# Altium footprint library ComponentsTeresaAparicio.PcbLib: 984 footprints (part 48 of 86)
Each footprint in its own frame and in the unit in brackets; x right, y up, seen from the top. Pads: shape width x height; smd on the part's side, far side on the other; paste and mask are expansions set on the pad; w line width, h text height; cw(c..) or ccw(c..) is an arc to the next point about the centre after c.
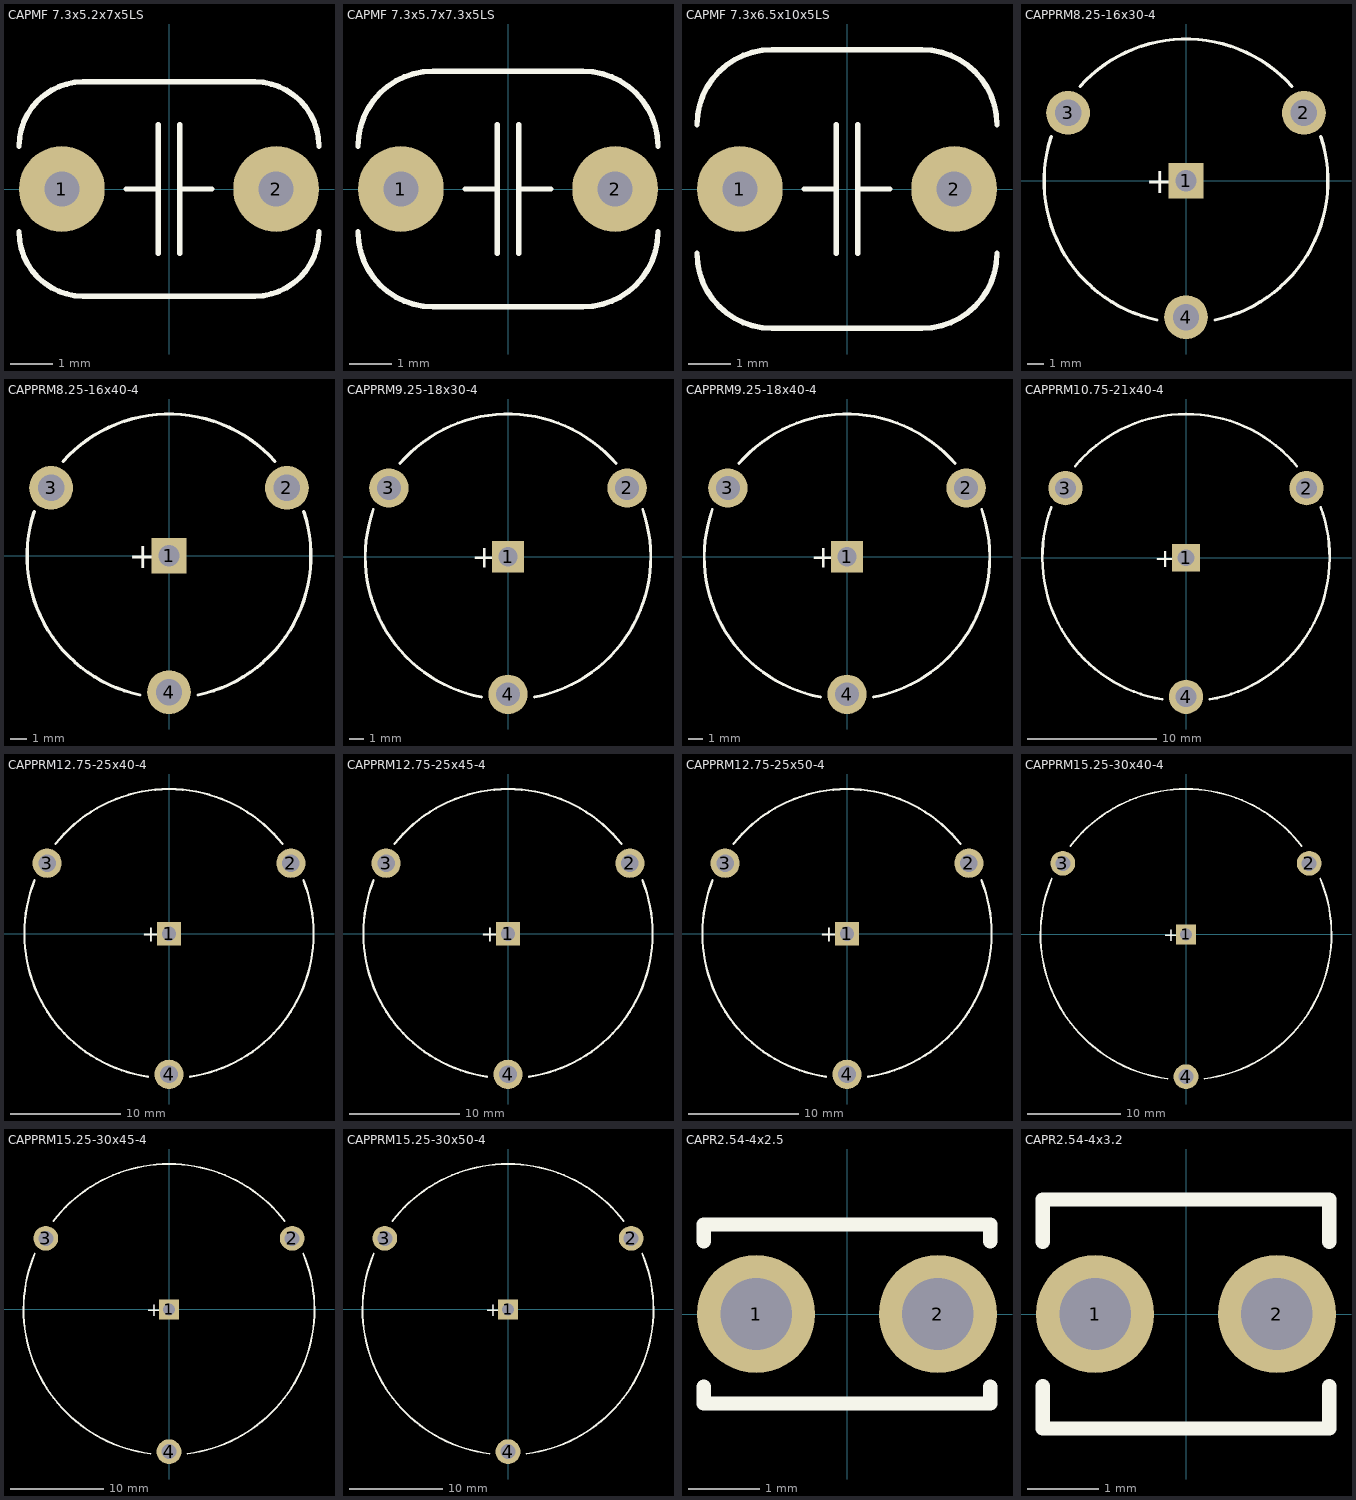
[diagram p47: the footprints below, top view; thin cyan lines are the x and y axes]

## CAPMF 7.3x5.2x7x5LS [mm] "Capacitor, THT, Metallized Polyester Film"
height 7
pads (2):
  round 2 hole 0.813: 1(-2.5,0) 2(2.5,0)
Top Overlay:
  lines w0.127: -3.5,-1 ccw(c-2,-1) -2,-2.5 2,-2.5 ccw(c2,-1) 3.5,-1 ; -3.5,1 cw(c-2,1) -2,2.5 2,2.5 cw(c2,1) 3.5,1 ; -1,0 -0.25,0 ; -0.25,-1.5 -0.25,1.5 ; 0.25,-1.5 0.25,1.5 ; 0.25,0 1,0
3D body: height 8, standoff -2, extent -3.65,-2.6 3.65,2.6

## CAPMF 7.3x5.7x7.3x5LS [mm] "Capacitor, THT, Metallized Polyester Film"
height 7
pads (2):
  round 2 hole 0.813: 1(-2.5,0) 2(2.5,0)
Top Overlay:
  lines w0.127: -3.5,-1 ccw(c-1.75,-1) -1.75,-2.75 1.75,-2.75 ccw(c1.75,-1) 3.5,-1 ; -3.5,1 cw(c-1.75,1) -1.75,2.75 1.75,2.75 cw(c1.75,1) 3.5,1 ; -1,0 -0.25,0 ; -0.25,-1.5 -0.25,1.5 ; 0.25,-1.5 0.25,1.5 ; 0.25,0 1,0
3D body: height 8.3, standoff -2, extent -3.65,-2.85 3.65,2.85

## CAPMF 7.3x6.5x10x5LS [mm] "Capacitor, THT, Metallized Polyester Film"
height 10
pads (2):
  round 2 hole 0.813: 1(-2.5,0) 2(2.5,0)
Top Overlay:
  lines w0.127: -3.5,-1.5 ccw(c-1.75,-1.5) -1.75,-3.25 1.75,-3.25 ccw(c1.75,-1.5) 3.5,-1.5 ; -3.5,1.5 cw(c-1.75,1.5) -1.75,3.25 1.75,3.25 cw(c1.75,1.5) 3.5,1.5 ; -1,0 -0.25,0 ; -0.25,-1.5 -0.25,1.5 ; 0.25,-1.5 0.25,1.5 ; 0.25,0 1,0
3D body: height 11, standoff -2, extent -3.65,-3.25 3.65,3.25

## CAPPRM8.25-16x30-4 [mm] "Capacitor, Electrolytic, Radial, Solder Ring; Body 16 x 30 mm (Dia.xH typ); Pin Spacing 8.25 mm (typ)"
height 32
pads (4):
  rect 2.15x2.15 hole 1.3: 1(0,0)
  round 2.65 hole 1.6: 2(7.145,4.125) 3(-7.145,4.125) 4(0,-8.25)
Top Overlay:
  lines w0.2: -8.168,2.692 ccw(c0,0) -1.752,-8.42 ; -6.415,5.727 cw(c0,0) 6.415,5.727 ; 1.752,-8.42 ccw(c0,0) 8.168,2.692
  text "+" at -2.45,-0.75 h1.5

## CAPPRM8.25-16x40-4 [mm] "Capacitor, Electrolytic, Radial, Solder Ring; Body 16 x 40 mm (Dia.xH typ); Pin Spacing 8.25 mm (typ)"
height 42
pads (4):
  rect 2.15x2.15 hole 1.3: 1(0,0)
  round 2.65 hole 1.6: 2(7.145,4.125) 3(-7.145,4.125) 4(0,-8.25)
Top Overlay:
  lines w0.2: -8.168,2.692 ccw(c0,0) -1.752,-8.42 ; -6.415,5.727 cw(c0,0) 6.415,5.727 ; 1.752,-8.42 ccw(c0,0) 8.168,2.692
  text "+" at -2.45,-0.75 h1.5

## CAPPRM9.25-18x30-4 [mm] "Capacitor, Electrolytic, Radial, Solder Ring; Body 18 x 30 mm (Dia.xH typ); Pin Spacing 9.25 mm (typ)"
height 32
pads (4):
  rect 2.15x2.15 hole 1.3: 1(0,0)
  round 2.65 hole 1.6: 2(8.011,4.625) 3(-8.011,4.625) 4(0,-9.25)
Top Overlay:
  lines w0.2: -9.062,3.17 ccw(c0,0) -1.786,-9.432 ; -7.276,6.263 cw(c0,0) 7.276,6.263 ; 1.786,-9.432 ccw(c0,0) 9.062,3.17
  text "+" at -2.45,-0.75 h1.5

## CAPPRM9.25-18x40-4 [mm] "Capacitor, Electrolytic, Radial, Solder Ring; Body 18 x 40 mm (Dia.xH typ); Pin Spacing 9.25 mm (typ)"
height 42
pads (4):
  rect 2.15x2.15 hole 1.3: 1(0,0)
  round 2.65 hole 1.6: 2(8.011,4.625) 3(-8.011,4.625) 4(0,-9.25)
Top Overlay:
  lines w0.2: -9.062,3.17 ccw(c0,0) -1.786,-9.432 ; -7.276,6.263 cw(c0,0) 7.276,6.263 ; 1.786,-9.432 ccw(c0,0) 9.062,3.17
  text "+" at -2.45,-0.75 h1.5

## CAPPRM10.75-21x40-4 [mm] "Capacitor, Electrolytic, Radial, Solder Ring; Body 21 x 40 mm (Dia.xH typ); Pin Spacing 10.75 mm (typ)"
height 42
pads (4):
  rect 2.15x2.15 hole 1.3: 1(0,0)
  round 2.65 hole 1.6: 2(9.31,5.375) 3(-9.31,5.375) 4(0,-10.75)
Top Overlay:
  lines w0.2: -10.398,3.883 ccw(c0,0) -1.836,-10.947 ; -8.562,7.064 cw(c0,0) 8.562,7.064 ; 1.836,-10.947 ccw(c0,0) 10.398,3.883
  text "+" at -2.45,-0.75 h1.5

## CAPPRM12.75-25x40-4 [mm] "Capacitor, Electrolytic, Radial, Solder Ring; Body 25 x 40 mm (Dia.xH typ); Pin Spacing 12.75 mm (typ)"
height 42
pads (4):
  rect 2.15x2.15 hole 1.3: 1(0,0)
  round 2.65 hole 1.6: 2(11.042,6.375) 3(-11.042,6.375) 4(0,-12.75)
Top Overlay:
  lines w0.2: -12.176,4.832 ccw(c0,0) -1.904,-12.961 ; -10.273,8.129 cw(c0,0) 10.273,8.129 ; 1.904,-12.961 ccw(c0,0) 12.176,4.832
  text "+" at -2.45,-0.75 h1.5

## CAPPRM12.75-25x45-4 [mm] "Capacitor, Electrolytic, Radial, Solder Ring; Body 25 x 45 mm (Dia.xH typ); Pin Spacing 12.75 mm (typ)"
height 48
pads (4):
  rect 2.15x2.15 hole 1.3: 1(0,0)
  round 2.65 hole 1.6: 2(11.042,6.375) 3(-11.042,6.375) 4(0,-12.75)
Top Overlay:
  lines w0.2: -12.176,4.832 ccw(c0,0) -1.904,-12.961 ; -10.273,8.129 cw(c0,0) 10.273,8.129 ; 1.904,-12.961 ccw(c0,0) 12.176,4.832
  text "+" at -2.45,-0.75 h1.5

## CAPPRM12.75-25x50-4 [mm] "Capacitor, Electrolytic, Radial, Solder Ring; Body 25 x 50 mm (Dia.xH typ); Pin Spacing 12.75 mm (typ)"
height 53
pads (4):
  rect 2.15x2.15 hole 1.3: 1(0,0)
  round 2.65 hole 1.6: 2(11.042,6.375) 3(-11.042,6.375) 4(0,-12.75)
Top Overlay:
  lines w0.2: -12.176,4.832 ccw(c0,0) -1.904,-12.961 ; -10.273,8.129 cw(c0,0) 10.273,8.129 ; 1.904,-12.961 ccw(c0,0) 12.176,4.832
  text "+" at -2.45,-0.75 h1.5

## CAPPRM15.25-30x40-4 [mm] "Capacitor, Electrolytic, Radial, Solder Ring; Body 30 x 40 mm (Dia.xH typ); Pin Spacing 15.25 mm (typ)"
height 42
pads (4):
  rect 2.15x2.15 hole 1.3: 1(0,0)
  round 2.65 hole 1.6: 2(13.207,7.625) 3(-13.207,7.625) 4(0,-15.25)
Top Overlay:
  lines w0.2: -14.394,6.014 ccw(c0,0) -1.989,-15.473 ; -12.405,9.459 cw(c0,0) 12.405,9.459 ; 1.989,-15.473 ccw(c0,0) 14.394,6.014
  text "+" at -2.45,-0.75 h1.5

## CAPPRM15.25-30x45-4 [mm] "Capacitor, Electrolytic, Radial, Solder Ring; Body 30 x 45 mm (Dia.xH typ); Pin Spacing 15.25 mm (typ)"
height 48
pads (4):
  rect 2.15x2.15 hole 1.3: 1(0,0)
  round 2.65 hole 1.6: 2(13.207,7.625) 3(-13.207,7.625) 4(0,-15.25)
Top Overlay:
  lines w0.2: -14.394,6.014 ccw(c0,0) -1.989,-15.473 ; -12.405,9.459 cw(c0,0) 12.405,9.459 ; 1.989,-15.473 ccw(c0,0) 14.394,6.014
  text "+" at -2.45,-0.75 h1.5

## CAPPRM15.25-30x50-4 [mm] "Capacitor, Electrolytic, Radial, Solder Ring; Body 30 x 50 mm (Dia.xH typ); Pin Spacing 15.25 mm (typ)"
height 53
pads (4):
  rect 2.15x2.15 hole 1.3: 1(0,0)
  round 2.65 hole 1.6: 2(13.207,7.625) 3(-13.207,7.625) 4(0,-15.25)
Top Overlay:
  lines w0.2: -14.394,6.014 ccw(c0,0) -1.989,-15.473 ; -12.405,9.459 cw(c0,0) 12.405,9.459 ; 1.989,-15.473 ccw(c0,0) 14.394,6.014
  text "+" at -2.45,-0.75 h1.5

## CAPR2.54-4x2.5 [mm] "Capacitor, Ceramic, Thru-Hole, Dipped Radial; Body 4 x 2.5 mm (WxT) Pin Spacing 2.54 mm (typ)"
height 4.6
pads (2):
  round 1.65 hole 1: 1(-1.27,0) 2(1.27,0)
Top Overlay:
  lines w0.2: -2,-1.015 -2,-1.25 2,-1.25 2,-1.015 ; -2,1.015 -2,1.25 2,1.25 2,1.015

## CAPR2.54-4x3.2 [mm] "Capacitor, Ceramic, Thru-Hole, Dipped Radial; Body 4 x 3.2 mm (WxT) Pin Spacing 2.54 mm (typ)"
height 4.6
pads (2):
  round 1.65 hole 1: 1(-1.27,0) 2(1.27,0)
Top Overlay:
  lines w0.2: -2,-1.01 -2,-1.6 2,-1.6 2,-1.01 ; -2,1.01 -2,1.6 2,1.6 2,1.01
